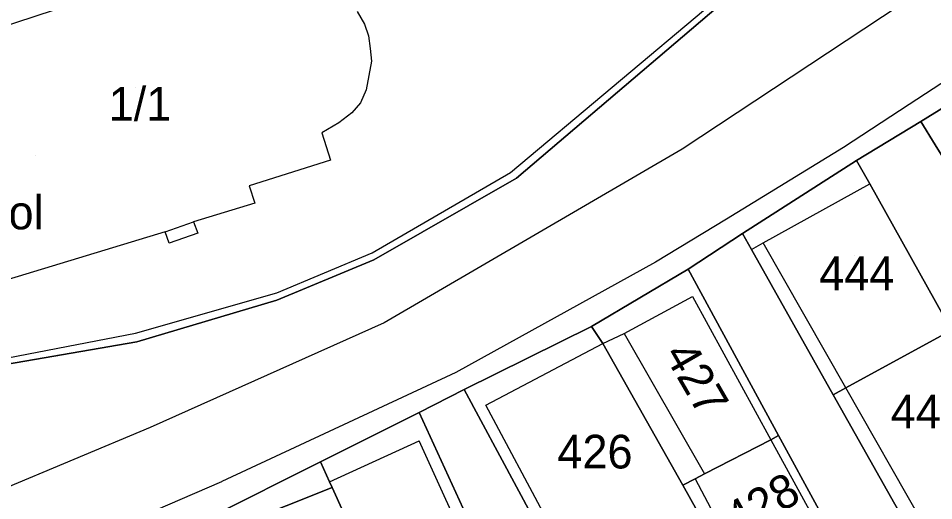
# Model space of a CAD drawing. Extents: x -263943 to -261149, y -1236934 to -1230686.
# Drawn here: x -262849 to -262794.6, y -1235500.9 to -1235472.3 of the extents above; entities that cross this region are included whole.
import ezdxf

# ---------------------------------------------------------------- set-up
doc = ezdxf.new("R2010")
doc.units = 0
for name, color, linetype in [('body_kn', 7, 'Continuous'), ('kladpar_druhypozemkov', 7, 'Continuous'), ('kladpar_hranice', 7, 'Continuous'), ('kladpar_parcelnecisla', 7, 'Continuous'), ('kladpar_plochy', 7, 'Continuous'), ('popisy', 7, 'Continuous'), ('zappar_hrandruhpozemk', 7, 'Continuous'), ('znacky', 7, 'Continuous')]:
    doc.layers.add(name, color=color, linetype=linetype)

msp = doc.modelspace()

# ---------------------------------------------------------------- linework, layer by layer
at = {"layer": 'body_kn'}
for p, q in [((-262828.42, -1235472.68), (-262828.42, -1235472.68)), ((-262828.17, -1235473.36), (-262828.17, -1235473.36)), ((-262828.08, -1235474.12), (-262828.08, -1235474.12)), ((-262827.99, -1235474.88), (-262827.99, -1235474.88)), ((-262828.16, -1235475.73), (-262828.16, -1235475.73)), ((-262828.32, -1235476.58), (-262828.32, -1235476.58)), ((-262828.66, -1235477.34), (-262828.66, -1235477.34)), ((-262796.08, -1235477.45), (-262796.08, -1235477.45)), ((-262829.17, -1235477.94), (-262829.17, -1235477.94)), ((-262829.93, -1235478.53), (-262829.93, -1235478.53)), ((-262795.4, -1235478.46), (-262795.4, -1235478.46)), ((-262830.94, -1235479.13), (-262830.94, -1235479.13)), ((-262809.56, -1235480.1), (-262809.56, -1235480.1)), ((-262799.98, -1235480), (-262799.98, -1235480)), ((-262830.43, -1235480.74), (-262830.43, -1235480.74)), ((-262799.21, -1235480.76), (-262799.21, -1235480.76)), ((-262819.74, -1235481.48), (-262819.74, -1235481.48)), ((-262819.4, -1235481.82), (-262819.4, -1235481.82)), ((-262835.26, -1235482.27), (-262835.26, -1235482.27)), ((-262798.43, -1235482.16), (-262798.43, -1235482.16)), ((-262834.92, -1235483.29), (-262834.92, -1235483.29)), ((-262806.92, -1235484.25), (-262806.92, -1235484.25)), ((-262838.56, -1235484.4), (-262838.56, -1235484.4)), ((-262840.25, -1235484.99), (-262840.25, -1235484.99)), ((-262840.25, -1235484.99), (-262840.25, -1235484.99)), ((-262838.3, -1235485.07), (-262838.3, -1235485.07)), ((-262805.98, -1235485.09), (-262805.98, -1235485.09)), ((-262840, -1235485.67), (-262840, -1235485.67)), ((-262804.76, -1235485.66), (-262804.76, -1235485.66)), ((-262804.76, -1235485.66), (-262804.76, -1235485.66)), ((-262827.95, -1235486.24), (-262827.95, -1235486.24)), ((-262805.45, -1235486.04), (-262805.45, -1235486.04)), ((-262805.45, -1235486.04), (-262805.45, -1235486.04)), ((-262827.86, -1235486.66), (-262827.86, -1235486.66)), ((-262811.15, -1235486.8), (-262811.15, -1235486.8)), ((-262809.2, -1235487.22), (-262809.2, -1235487.22)), ((-262833.62, -1235488.62), (-262833.62, -1235488.62)), ((-262833.62, -1235489.05), (-262833.62, -1235489.05)), ((-262808.94, -1235488.83), (-262808.94, -1235488.83)), ((-262808.94, -1235488.83), (-262808.94, -1235488.83)), ((-262827.25, -1235490.39), (-262827.25, -1235490.39)), ((-262814.95, -1235490.62), (-262814.95, -1235490.62)), ((-262842.01, -1235491.01), (-262842.01, -1235491.01)), ((-262813, -1235491.04), (-262813, -1235491.04)), ((-262841.93, -1235491.52), (-262841.93, -1235491.52)), ((-262814.27, -1235491.63), (-262814.27, -1235491.63)), ((-262814.27, -1235491.63), (-262814.27, -1235491.63)), ((-262823, -1235493.35), (-262823, -1235493.35)), ((-262822.49, -1235494.36), (-262822.49, -1235494.36)), ((-262799.85, -1235494.25), (-262799.85, -1235494.25)), ((-262799.85, -1235494.25), (-262799.85, -1235494.25)), ((-262800.6, -1235494.66), (-262800.6, -1235494.66)), ((-262825.17, -1235495.71), (-262825.17, -1235495.71)), ((-262821.21, -1235495.29), (-262821.21, -1235495.29)), ((-262821.21, -1235495.29), (-262821.21, -1235495.29)), ((-262841.14, -1235496.6), (-262841.14, -1235496.6)), ((-262841.14, -1235496.6), (-262841.14, -1235496.6)), ((-262804.3, -1235497.33), (-262804.3, -1235497.33)), ((-262804.3, -1235497.33), (-262804.3, -1235497.33)), ((-262803.84, -1235497.09), (-262803.84, -1235497.09)), ((-262825.16, -1235497.39), (-262825.16, -1235497.39)), ((-262831.03, -1235498.65), (-262831.03, -1235498.65)), ((-262808.23, -1235499.36), (-262808.23, -1235499.36)), ((-262808.23, -1235499.36), (-262808.23, -1235499.36)), ((-262836.89, -1235499.81), (-262836.89, -1235499.81)), ((-262830.49, -1235499.84), (-262830.49, -1235499.84)), ((-262830.49, -1235499.84), (-262830.49, -1235499.84)), ((-262809.52, -1235500.03), (-262809.52, -1235500.03)), ((-262808.79, -1235499.65), (-262808.79, -1235499.65)), ((-262808.79, -1235499.65), (-262808.79, -1235499.65)), ((-262830.34, -1235500.17), (-262830.34, -1235500.17)), ((-262830.34, -1235500.17), (-262830.34, -1235500.17))]:
    msp.add_line(p, q, dxfattribs=at)
at = {"layer": 'kladpar_druhypozemkov'}
for p, q in [((-262842, -1235476.41), (-262842, -1235476.41)), ((-262799.33, -1235486.41), (-262799.33, -1235486.41)), ((-262807.61, -1235493.2), (-262807.61, -1235493.2)), ((-262815.02, -1235496.94), (-262815.02, -1235496.94)), ((-262805.34, -1235500.68), (-262805.34, -1235500.68))]:
    msp.add_line(p, q, dxfattribs=at)
at = {"layer": 'kladpar_hranice'}
for points in [[(-262745.47, -1235446.26), (-262755.37, -1235452.8), (-262762.56, -1235457.56), (-262766.45, -1235460.19), (-262766.89, -1235460.48), (-262774.6, -1235465.48), (-262775.09, -1235465.8), (-262778.05, -1235467.58), (-262784.31, -1235471.58), (-262788.54, -1235474.21), (-262795.4, -1235478.46), (-262799.21, -1235480.76), (-262805.98, -1235485.09), (-262809.2, -1235487.22), (-262814.95, -1235490.62), (-262822.49, -1235494.36), (-262825.17, -1235495.71), (-262831.03, -1235498.65), (-262837.57, -1235501.93)], [(-262851.34, -1235493.15), (-262841.93, -1235491.52), (-262833.62, -1235489.05), (-262827.86, -1235486.66), (-262819.4, -1235481.82), (-262801.55, -1235466.61), (-262795.8, -1235461.6), (-262798.28, -1235456.61), (-262804.72, -1235458.82), (-262840.66, -1235465.59)], [(-262801.64, -1235466.27), (-262801.55, -1235466.61), (-262819.4, -1235481.82), (-262827.86, -1235486.66), (-262833.62, -1235489.05), (-262841.93, -1235491.52), (-262851.34, -1235493.15)], [(-262789.34, -1235486.86), (-262789.96, -1235487.22), (-262794.54, -1235479.84), (-262795.4, -1235478.46), (-262788.54, -1235474.21), (-262787.61, -1235475.8), (-262783.21, -1235483.3), (-262783.74, -1235483.61), (-262789.34, -1235486.86)], [(-262787.3, -1235502.76), (-262788.87, -1235500.01), (-262788.39, -1235499.76), (-262793.57, -1235490.83), (-262798.43, -1235482.16), (-262799.21, -1235480.76), (-262795.4, -1235478.46), (-262794.54, -1235479.84), (-262789.96, -1235487.22), (-262782.17, -1235499.78), (-262782.05, -1235499.71), (-262776.26, -1235509.44)], [(-262799.85, -1235494.25), (-262800.6, -1235494.66), (-262805.45, -1235486.04), (-262805.98, -1235485.09), (-262799.21, -1235480.76), (-262798.43, -1235482.16), (-262793.57, -1235490.83), (-262799.85, -1235494.25)], [(-262801.45, -1235501.48), (-262803.84, -1235497.09), (-262809.2, -1235487.22), (-262805.98, -1235485.09), (-262805.45, -1235486.04), (-262800.6, -1235494.66), (-262795.64, -1235503.48)], [(-262808.23, -1235499.36), (-262808.79, -1235499.65), (-262809.52, -1235500.03), (-262814.27, -1235491.63), (-262814.95, -1235490.62), (-262809.2, -1235487.22), (-262803.84, -1235497.09), (-262804.3, -1235497.33), (-262808.23, -1235499.36)], [(-262808.66, -1235501.55), (-262815.7, -1235505.57), (-262816.28, -1235505.9), (-262822.49, -1235494.36), (-262814.95, -1235490.62), (-262814.27, -1235491.63), (-262809.52, -1235500.03), (-262808.66, -1235501.55)], [(-262794.82, -1235503.06), (-262795.64, -1235503.48), (-262800.6, -1235494.66), (-262799.85, -1235494.25), (-262793.57, -1235490.83), (-262788.39, -1235499.76), (-262788.87, -1235500.01), (-262794.82, -1235503.06)], [(-262821.26, -1235504.26), (-262825.17, -1235495.71), (-262822.49, -1235494.36), (-262816.28, -1235505.9)], [(-262819.84, -1235505.98), (-262820.36, -1235506.23), (-262821.01, -1235506.54), (-262826.31, -1235509.06), (-262826.46, -1235508.74), (-262828.42, -1235504.4), (-262830.34, -1235500.17), (-262830.49, -1235499.84), (-262831.03, -1235498.65), (-262825.17, -1235495.71), (-262821.26, -1235504.26), (-262820.85, -1235504.02), (-262819.84, -1235505.98)], [(-262804.33, -1235508.09), (-262804.95, -1235508.45), (-262807.05, -1235504.54), (-262808.66, -1235501.55), (-262809.52, -1235500.03), (-262808.79, -1235499.65), (-262808.23, -1235499.36), (-262804.3, -1235497.33), (-262803.84, -1235497.09), (-262801.45, -1235501.48), (-262799.41, -1235505.23), (-262799.84, -1235505.48), (-262804.33, -1235508.09)], [(-262837.57, -1235501.93), (-262831.03, -1235498.65), (-262830.49, -1235499.84), (-262830.34, -1235500.17), (-262835.79, -1235502.34)], [(-262830.34, -1235500.17), (-262828.42, -1235504.4), (-262826.46, -1235508.74), (-262826.31, -1235509.06), (-262824.26, -1235513.59), (-262822.98, -1235516.41), (-262828.57, -1235518.88), (-262829.62, -1235519.34), (-262831.58, -1235514.88), (-262831.8, -1235514.37), (-262832.13, -1235513.64), (-262833.04, -1235511.56), (-262833.74, -1235509.98), (-262834.96, -1235507.19), (-262836.89, -1235502.78), (-262835.79, -1235502.34), (-262830.34, -1235500.17)]]:
    msp.add_lwpolyline(points, dxfattribs=at)
at = {"layer": 'kladpar_plochy'}
for p, q in [((-262819.4, -1235481.82), (-262801.55, -1235466.61)), ((-262788.54, -1235474.21), (-262795.4, -1235478.46)), ((-262795.4, -1235478.46), (-262799.21, -1235480.76)), ((-262799.21, -1235480.76), (-262795.4, -1235478.46)), ((-262795.4, -1235478.46), (-262794.54, -1235479.84)), ((-262799.21, -1235480.76), (-262805.98, -1235485.09)), ((-262798.43, -1235482.16), (-262799.21, -1235480.76)), ((-262827.86, -1235486.66), (-262819.4, -1235481.82)), ((-262793.57, -1235490.83), (-262798.43, -1235482.16)), ((-262805.98, -1235485.09), (-262809.2, -1235487.22)), ((-262833.62, -1235489.05), (-262827.86, -1235486.66)), ((-262809.2, -1235487.22), (-262814.95, -1235490.62)), ((-262841.93, -1235491.52), (-262833.62, -1235489.05)), ((-262814.95, -1235490.62), (-262822.49, -1235494.36)), ((-262851.34, -1235493.15), (-262841.93, -1235491.52)), ((-262822.49, -1235494.36), (-262825.17, -1235495.71)), ((-262825.17, -1235495.71), (-262831.03, -1235498.65)), ((-262831.03, -1235498.65), (-262837.57, -1235501.93))]:
    msp.add_line(p, q, dxfattribs=at)
for points in [[(-262858.54, -1235471.55), (-262840.66, -1235465.59), (-262804.72, -1235458.82), (-262804.55, -1235459.16), (-262801.64, -1235466.27), (-262801.55, -1235466.61), (-262819.4, -1235481.82), (-262827.86, -1235486.66), (-262833.62, -1235489.05), (-262841.93, -1235491.52), (-262851.34, -1235493.15)], [(-262801.45, -1235501.48), (-262803.84, -1235497.09), (-262809.2, -1235487.22), (-262805.98, -1235485.09), (-262805.45, -1235486.04), (-262800.6, -1235494.66), (-262795.64, -1235503.48)], [(-262821.26, -1235504.26), (-262825.17, -1235495.71), (-262822.49, -1235494.36), (-262816.28, -1235505.9)], [(-262837.57, -1235501.93), (-262831.03, -1235498.65), (-262830.49, -1235499.84), (-262830.34, -1235500.17), (-262835.79, -1235502.34)]]:
    msp.add_lwpolyline(points, dxfattribs=at)
for points in [[(-262789.34, -1235486.86), (-262789.96, -1235487.22), (-262794.54, -1235479.84), (-262795.4, -1235478.46), (-262788.54, -1235474.21), (-262787.61, -1235475.8), (-262783.21, -1235483.3), (-262783.74, -1235483.61)], [(-262799.85, -1235494.25), (-262800.6, -1235494.66), (-262805.45, -1235486.04), (-262805.98, -1235485.09), (-262799.21, -1235480.76), (-262798.43, -1235482.16), (-262793.57, -1235490.83)], [(-262808.23, -1235499.36), (-262808.79, -1235499.65), (-262809.52, -1235500.03), (-262814.27, -1235491.63), (-262814.95, -1235490.62), (-262809.2, -1235487.22), (-262803.84, -1235497.09), (-262804.3, -1235497.33)], [(-262808.66, -1235501.55), (-262815.7, -1235505.57), (-262816.28, -1235505.9), (-262822.49, -1235494.36), (-262814.95, -1235490.62), (-262814.27, -1235491.63), (-262809.52, -1235500.03)], [(-262794.82, -1235503.06), (-262795.64, -1235503.48), (-262800.6, -1235494.66), (-262799.85, -1235494.25), (-262793.57, -1235490.83), (-262788.39, -1235499.76), (-262788.87, -1235500.01)], [(-262819.84, -1235505.98), (-262820.36, -1235506.23), (-262821.01, -1235506.54), (-262826.31, -1235509.06), (-262826.46, -1235508.74), (-262828.42, -1235504.4), (-262830.34, -1235500.17), (-262830.49, -1235499.84), (-262831.03, -1235498.65), (-262825.17, -1235495.71), (-262821.26, -1235504.26), (-262820.85, -1235504.02)], [(-262804.33, -1235508.09), (-262804.95, -1235508.45), (-262807.05, -1235504.54), (-262808.66, -1235501.55), (-262809.52, -1235500.03), (-262808.79, -1235499.65), (-262808.23, -1235499.36), (-262804.3, -1235497.33), (-262803.84, -1235497.09), (-262801.45, -1235501.48), (-262799.41, -1235505.23), (-262799.84, -1235505.48)], [(-262830.34, -1235500.17), (-262828.42, -1235504.4), (-262826.46, -1235508.74), (-262826.31, -1235509.06), (-262824.26, -1235513.59), (-262822.98, -1235516.41), (-262828.57, -1235518.88), (-262829.62, -1235519.34), (-262831.58, -1235514.88), (-262831.8, -1235514.37), (-262832.13, -1235513.64), (-262833.04, -1235511.56), (-262833.74, -1235509.98), (-262834.96, -1235507.19), (-262836.89, -1235502.78), (-262835.79, -1235502.34)]]:
    msp.add_lwpolyline(points, close=True, dxfattribs=at)
at = {"layer": 'zappar_hrandruhpozemk'}
for p, q in [((-262854.21, -1235474.26), (-262839.46, -1235469.4)), ((-262809.56, -1235480.1), (-262827.25, -1235490.39)), ((-262804.76, -1235485.66), (-262798.43, -1235482.16)), ((-262840.25, -1235484.99), (-262838.56, -1235484.4)), ((-262805.45, -1235486.04), (-262804.76, -1235485.66)), ((-262799.85, -1235494.25), (-262804.76, -1235485.66)), ((-262811.15, -1235486.8), (-262823, -1235493.35)), ((-262842.01, -1235491.01), (-262833.62, -1235488.62)), ((-262813, -1235491.04), (-262808.94, -1235488.83)), ((-262808.94, -1235488.83), (-262804.3, -1235497.33)), ((-262827.25, -1235490.39), (-262841.14, -1235496.6)), ((-262814.27, -1235491.63), (-262813, -1235491.04)), ((-262813, -1235491.04), (-262808.23, -1235499.36)), ((-262821.21, -1235495.29), (-262814.27, -1235491.63)), ((-262823, -1235493.35), (-262836.89, -1235499.81)), ((-262794.82, -1235503.06), (-262799.85, -1235494.25)), ((-262815.7, -1235505.57), (-262821.21, -1235495.29)), ((-262841.14, -1235496.6), (-262901.32, -1235521.91)), ((-262830.49, -1235499.84), (-262825.16, -1235497.39)), ((-262847.25, -1235504.27), (-262836.89, -1235499.81))]:
    msp.add_line(p, q, dxfattribs=at)
for points in [[(-262686.74, -1235403.46), (-262715.86, -1235420.37), (-262741.68, -1235435.75), (-262772.15, -1235455.63), (-262791.2, -1235467.95), (-262809.56, -1235480.1)], [(-262685.11, -1235407.86), (-262717.88, -1235426.64), (-262739.97, -1235440.83), (-262767.48, -1235458.75), (-262796.08, -1235477.45), (-262799.98, -1235480), (-262806.92, -1235484.25), (-262811.15, -1235486.8)], [(-262833.62, -1235488.62), (-262827.95, -1235486.24), (-262819.74, -1235481.48), (-262801.64, -1235466.27)], [(-262828.85, -1235471.92), (-262828.42, -1235472.68), (-262828.17, -1235473.36), (-262828.08, -1235474.12), (-262827.99, -1235474.88), (-262828.16, -1235475.73), (-262828.32, -1235476.58), (-262828.66, -1235477.34), (-262829.17, -1235477.94), (-262829.93, -1235478.53), (-262830.94, -1235479.13), (-262830.43, -1235480.74), (-262835.26, -1235482.27), (-262834.92, -1235483.29), (-262838.56, -1235484.4), (-262838.3, -1235485.07), (-262840, -1235485.67), (-262840.25, -1235484.99), (-262850.09, -1235487.98)], [(-262870.95, -1235489.04), (-262870.44, -1235488.86), (-262867.21, -1235491.06), (-262864.92, -1235492.16), (-262861.6, -1235493.34), (-262857.02, -1235493.24), (-262851.34, -1235492.81), (-262842.01, -1235491.01)], [(-262804.3, -1235497.33), (-262801.9, -1235501.72), (-262799.84, -1235505.48)], [(-262821.01, -1235506.54), (-262821.88, -1235504.62), (-262825.16, -1235497.39)], [(-262808.79, -1235499.65), (-262806.39, -1235504.18), (-262804.33, -1235508.09)]]:
    msp.add_lwpolyline(points, dxfattribs=at)
at = {"layer": 'znacky'}
msp.add_line((-262847.97, -1235480.46), (-262847.97, -1235480.46), dxfattribs=at)

# ---------------------------------------------------------------- texts
at = {"layer": 'kladpar_parcelnecisla'}
for s, p in [('1/1', (-262843.598, -1235478.41)), ('444', (-262801.429, -1235488.46)), ('443', (-262797.181, -1235496.66)), ('426', (-262816.966, -1235499.04))]:
    msp.add_text(s, height=2, dxfattribs=at).set_placement(p)
for s, rotation, p in [('427', 300, (-262810.675, -1235492.265)), ('428', 29, (-262806.302, -1235503.093))]:
    msp.add_text(s, height=2, rotation=rotation, dxfattribs=at).set_placement(p)
at = {"layer": 'popisy'}
msp.add_text('Kostol', height=2, dxfattribs=at).set_placement((-262854.897, -1235484.85))

doc.saveas('drawing.dxf')
